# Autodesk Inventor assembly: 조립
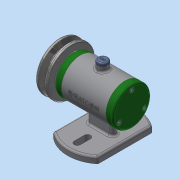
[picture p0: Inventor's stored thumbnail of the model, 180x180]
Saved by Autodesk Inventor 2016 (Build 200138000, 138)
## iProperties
Created: 2017-12
Part Number: 조립
Material: 일반
Document SubType Name: Assembly
Designer: 605-07
Author: 605-07
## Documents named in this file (14)
- C:\Users\605-07\Desktop\471207V1013\조립.iam
- C:\Users\605-07\Desktop\471207V1013\본체.ipt
- C:\Users\605-07\Desktop\471207V1013\고무캡.ipt
- C:\Users\605-07\Desktop\471207V1013\V벨트풀리.ipt
- C:\Users\605-07\Desktop\471207V1013\뒤커버.ipt
- C:\Users\605-07\Desktop\471207V1013\베어링 15 x 32 x 9.ipt
- C:\Users\605-07\Desktop\471207V1013\축.ipt
- C:\Users\605-07\Desktop\471207V1013\키 3 x 3 x 12.ipt
- C:\Users\605-07\Desktop\471207V1013\앞커버.ipt
- C:\Users\605-07\Desktop\471207V1013\오일 실 15 25 7.ipt
- C:\Users\605-07\Desktop\471207V1013\너트 M 8.ipt
- C:\Users\605-07\Desktop\471207V1013\스프링와셔 8.ipt
- C:\Users\605-07\Desktop\471207V1013\와셔 8x17.ipt
- C:\Users\605-07\Desktop\471207V1013\볼트 M4 x 12.ipt
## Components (2 placed, 2 different names)
1. 고무캡:1
2. V벨트풀리:1 — 각도:2
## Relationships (1: Angle 1)
- 각도:2 [Angle]: V벨트풀리:1
